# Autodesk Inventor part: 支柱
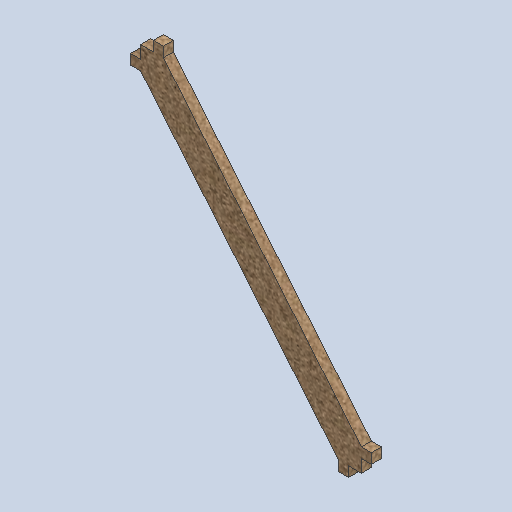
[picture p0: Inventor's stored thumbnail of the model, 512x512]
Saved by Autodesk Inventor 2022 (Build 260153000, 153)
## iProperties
Created: 2024-12
Part Number: 支柱
Material: MDF 中密度繊維ボード
Document SubType Name: Modeling
Designer: shimizu
Density: 0.8 g/cm^3
Appearance: ダンボール - 段ボール紙
Author: shimizu
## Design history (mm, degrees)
sketch "スケッチ1"
  geometry: L1 (-30.797, 30.211)-(-25.116, 30.211); L2 (-25.116, 30.211)-(-25.116, 24.53); L3 (-25.116, 24.53)-(-30.797, 24.53); L4 (-30.797, 24.53)-(-30.797, 30.211); L5 (18.522, -29.109)-(24.203, -29.109); L6 (24.203, -29.109)-(24.203, -34.789); L7 (24.203, -34.789)-(18.522, -34.789); L8 (18.522, -34.789)-(18.522, -29.109); L9 (-30.797, 24.53)-(18.522, -34.789); L10 (-25.116, 30.211)-(24.203, -29.109); L11 (-30.797, 24.53)-(-33.297, 24.53); L12 (-33.297, 24.53)-(-33.297, 27.03); L13 (-33.297, 27.03)-(-30.797, 27.03); L14 (-30.797, 27.03)-(-30.797, 24.53); L15 (-25.116, 30.211)-(-27.616, 30.211); L16 (-27.616, 30.211)-(-27.616, 32.711); L17 (-27.616, 32.711)-(-25.116, 32.711); L18 (-25.116, 32.711)-(-25.116, 30.211); L19 (18.522, -34.789)-(21.022, -34.789); L20 (21.022, -34.789)-(21.022, -37.289); L21 (21.022, -37.289)-(18.522, -37.289); L22 (18.522, -37.289)-(18.522, -34.789); L23 (24.203, -29.109)-(26.703, -29.109); L24 (26.703, -29.109)-(26.703, -31.609); L25 (26.703, -31.609)-(24.203, -31.609); L26 (24.203, -31.609)-(24.203, -29.109); 5 further points
  constraints: 52 end point, 13 parallel, 8 perpendicular, 6 horizontal
  dimensions: "d0" = 8 distance between parallel lines of L9 L10; "d1" = 55 distance between parallel lines of L6 L4; "d2" = 65 distance between parallel lines of L7 L1; "d3" = 2.5 distance of L11.end L12.end; "d4" = 2.5 distance of L3.end L11.end; "d5" = 2.5 distance of L17.end L1.end; "d6" = 2.5 distance of L16.end L17.end; "d7" = 2.5 distance of L21.end L7.end; "d8" = 2.5 distance of L20.end L21.end; "d9" = 2.5 distance of L23.end L24.end; "d10" = 2.5 distance of L5.end L23.end
extrude "押し出し1" new body sketch "スケッチ1" distance "d11" = 2.5; taper "d12" = 0 deg
node "ソリッド1"
